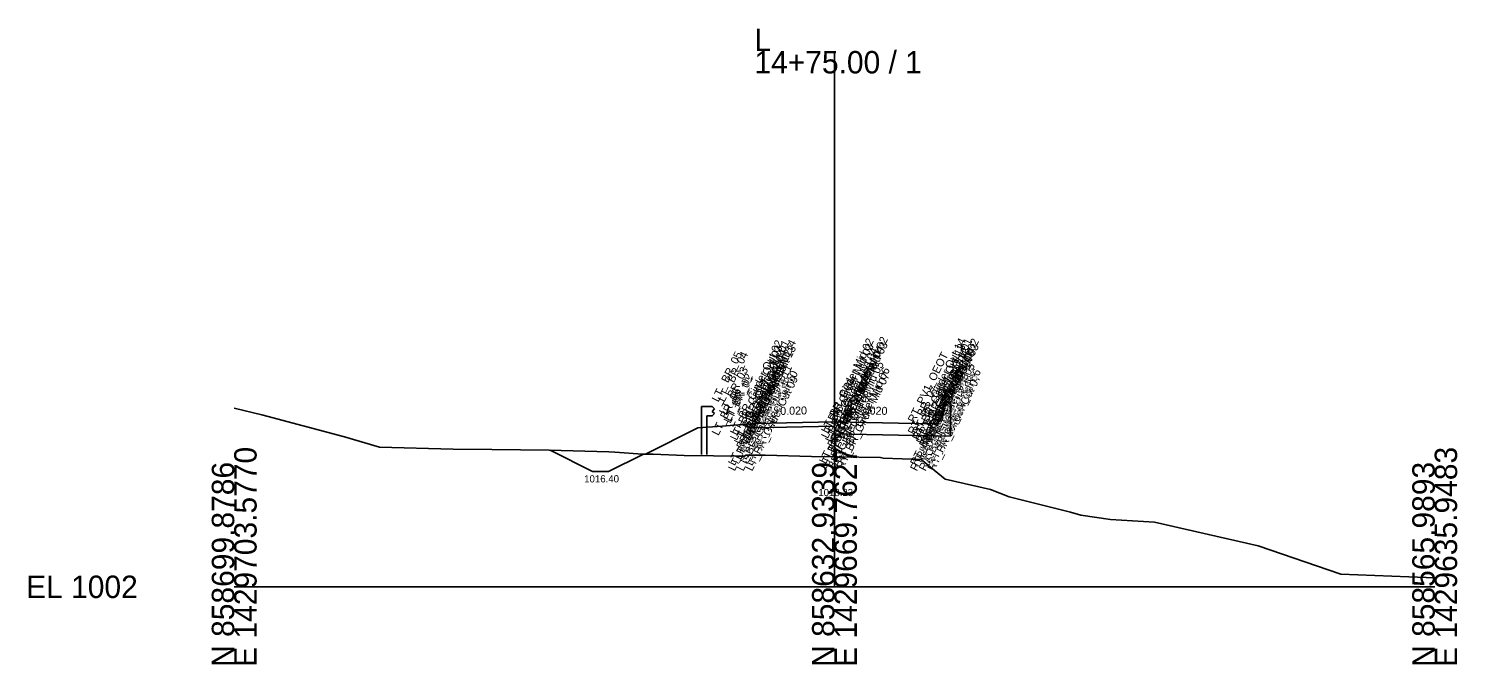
# Model space of a CAD drawing. Extents: x -26 to 153, y -10 to 13058.
# Drawn here: x -25.7 to 152.8, y 6490.3 to 6569.7 of the extents above; entities that cross this region are included whole.
import ezdxf

# ---------------------------------------------------------------- set-up
doc = ezdxf.new("R2010")
doc.units = 0
for name, color, linetype in [('Default', 7, 'Continuous'), ('Exist Cross Section Cell', 7, 'Continuous'), ('Exist XS Center Line Elevation Label', 7, 'Continuous'), ('Exist XS Ground Line', 7, 'Continuous'), ('Prop CMT Concrete Structures', 7, 'Continuous'), ('Prop CMT Guardrail Graphics', 7, 'Continuous'), ('Prop CMT Pvmt Course 1', 7, 'Continuous'), ('Prop CMT Pvmt Surface', 7, 'Continuous'), ('Prop CMT Pvmt Surface Shoulder', 7, 'Continuous'), ('Prop CMT Shld Paved Course 1', 7, 'Continuous'), ('Prop CMT Slope Grass', 7, 'Continuous'), ('Prop CMT Subgrade Earthwork', 7, 'Continuous'), ('Prop XS Dump Level', 7, 'Continuous'), ('Prop XS SE Text', 7, 'Continuous')]:
    doc.layers.add(name, color=color, linetype=linetype)

msp = doc.modelspace()

# ---------------------------------------------------------------- linework, layer by layer
at = {"layer": 'Exist Cross Section Cell'}
for p, q in [((75, 6500), (75, 6566.93)), ((0, 6500), (75, 6500)), ((75, 6500), (150, 6500))]:
    msp.add_line(p, q, dxfattribs=at)
at = {"layer": 'Exist XS Ground Line'}
msp.add_lwpolyline([(0, 6522.31), (3.44, 6521.49), (13.79, 6518.72), (18.17, 6517.45), (27.35, 6517.18), (32.2, 6517.15), (39.36, 6517.05), (46.79, 6516.88), (47.56, 6516.84), (51.03, 6516.57), (52.33, 6516.56), (56.24, 6516.42), (59.9, 6516.38), (62.96, 6516.34), (63.78, 6516.33), (63.92, 6516.46), (66.35, 6516.43), (72.14, 6516.29), (75, 6516.23), (75.38, 6516.22), (80.77, 6516.15), (81.07, 6516.09), (85.84, 6515.89), (88.82, 6513.45), (94.51, 6512.15), (96.84, 6511.22), (104.48, 6509.34), (105.79, 6508.93), (109.51, 6508.39), (114.97, 6508.07), (127.95, 6505.12), (138.29, 6501.59), (146.77, 6501.25), (150, 6501.11)], dxfattribs=at)
at = {"layer": 'Prop CMT Concrete Structures'}
for points in [[(75, 6520.61), (85, 6520.41), (88, 6520.35), (88.01, 6520.6), (88.59, 6521.43), (88.76, 6523.01), (89.5, 6523.01), (89.5, 6518.82)], [(75, 6519.11), (75, 6520.61)], [(75, 6519.11), (75, 6520.61)], [(89.5, 6518.82), (85, 6518.91), (75, 6519.11)]]:
    msp.add_lwpolyline(points, dxfattribs=at)
at = {"layer": 'Prop CMT Guardrail Graphics'}
for points in [[(58.4, 6516.51), (58.4, 6522.51)], [(58.4, 6522.51), (59.73, 6522.51), (60, 6522.22)], [(60, 6522.22), (59.73, 6521.92)], [(59.73, 6521.92), (60, 6521.63)], [(60, 6521.63), (59.73, 6521.34), (59.06, 6521.34)], [(59.06, 6521.34), (59.06, 6516.51)]]:
    msp.add_lwpolyline(points, dxfattribs=at)
at = {"layer": 'Prop CMT Pvmt Course 1'}
msp.add_line((75, 6520.61), (75, 6516.23), dxfattribs=at)
for points in [[(75, 6520.61), (65, 6520.41)], [(65, 6520.41), (65, 6519.87)], [(65, 6519.87), (75, 6520.07)]]:
    msp.add_lwpolyline(points, dxfattribs=at)
at = {"layer": 'Prop CMT Pvmt Surface'}
msp.add_lwpolyline([(75, 6520.61), (65, 6520.41)], dxfattribs=at)
at = {"layer": 'Prop CMT Pvmt Surface Shoulder'}
msp.add_lwpolyline([(65, 6520.41), (65, 6520.41)], dxfattribs=at)
at = {"layer": 'Prop CMT Shld Paved Course 1'}
for points in [[(65, 6520.41), (64.45, 6519.85)], [(65, 6520.41), (65, 6520.41)], [(65, 6519.87), (65, 6520.41)], [(64.45, 6519.85), (65, 6519.87)]]:
    msp.add_lwpolyline(points, dxfattribs=at)
at = {"layer": 'Prop CMT Slope Grass'}
for p, q in [((44.78, 6514.4), (39.48, 6517.05)), ((46.78, 6514.4), (51.06, 6516.54)), ((51.39, 6516.57), (51.06, 6516.54)), ((46.78, 6514.4), (44.78, 6514.4))]:
    msp.add_line(p, q, dxfattribs=at)
for points in [[(60.95, 6520.08), (57.95, 6519.84)], [(65, 6520.41), (60.95, 6520.08)], [(57.95, 6519.84), (51.39, 6516.57)]]:
    msp.add_lwpolyline(points, dxfattribs=at)
at = {"layer": 'Prop CMT Subgrade Earthwork'}
for points in [[(64.45, 6519.85), (63.98, 6520.33)], [(75, 6520.07), (65, 6519.87)], [(65, 6519.87), (64.45, 6519.85)]]:
    msp.add_lwpolyline(points, dxfattribs=at)

# ---------------------------------------------------------------- texts
at = {"layer": 'Default'}
for s, height, p in [('1016.40', 0.9, (43.73, 6513.04)), ('-', 0.0001, (0, 6500))]:
    msp.add_text(s, height=height, dxfattribs=at).set_placement(p)
at = {"layer": 'Exist Cross Section Cell'}
for s, p in [('L', (65, 6566.93)), ('14+75.00 / 1', (65, 6564.13)), ('EL 1002', (-26, 6498.6))]:
    msp.add_text(s, height=2.8, dxfattribs=at).set_placement(p)
for s, p in [('E 1429703.5770', (2.8, 6490)), ('E 1429669.7627', (77.8, 6490)), ('E 1429635.9483', (152.8, 6490)), ('N 858699.8786', (0, 6490)), ('N 858632.9339', (75, 6490)), ('N 858565.9893', (150, 6490))]:
    msp.add_text(s, height=2.8, rotation=90, dxfattribs=at).set_placement(p)
at = {"layer": 'Exist XS Center Line Elevation Label'}
msp.add_text('1018.23', height=0.9, dxfattribs=at).set_placement((72.98, 6511.33))
msp.add_text('1018.23', height=0.9, dxfattribs=at).set_placement((72.98, 6511.33))
msp.add_text('1018.23', height=0.9, dxfattribs=at).set_placement((72.98, 6511.33))
at = {"layer": 'Prop XS Dump Level'}
for s, p in [('LT_BR_Girder Out 02', (62.79, 6518.86)), ('LT_BR_Girder Out 14', (64.46, 6518.9)), ('LT_BR_Girder Mid 02', (74.17, 6519.09)), ('RT_BR_Girder Mid 02', (75.83, 6519.09)), ('RT_BR_Girder Out 14', (85.54, 6518.9)), ('RT_BR_Girder Out 01', (86.38, 6518.88)), ('RT_BR_Girder Out 02', (87.21, 6518.86)), ('LT_ BR_05', (60.5, 6523.01)), ('LT_ BR_04', (61.24, 6523.01)), ('LT_BR_Girder Out 03', (62.79, 6518.21)), ('LT_BR_Girder Out 04', (63.29, 6517.71)), ('LT_BR_Girder Out 01', (63.62, 6518.88)), ('LT_BR_Girder Out 12', (63.96, 6517.71)), ('LT_BR_Girder Out 13', (64.46, 6518.21)), ('LT_PV1_OEOT', (65, 6520.41)), ('LT_BR_Girder Mid 03', (74.17, 6518.44)), ('LT_BR_Girder Mid 04', (74.67, 6517.94)), ('RT_BR_Girder Mid 04', (75.33, 6517.94)), ('RT_BR_Girder Mid 03', (75.83, 6518.44)), ('RT_PV1_OEOT', (85, 6520.41)), ('RT_BR_Girder Out 13', (85.54, 6518.21)), ('RT_BR_Girder Out 12', (86.04, 6517.71)), ('RT_BR_Girder Out 04', (86.71, 6517.71)), ('RT_BR_Girder Out 03', (87.21, 6518.21)), ('RT_ BR_04', (88.76, 6523.01)), ('RT_ BR_05', (89.5, 6523.01)), ('LT_BR_03', (61.41, 6521.43)), ('LT_BR_Girder Out 05', (63.29, 6515.8)), ('LT_BR_Girder Out 11', (63.96, 6515.8)), ('LT_BR_Girder Mid 06', (73.92, 6515.27)), ('LT_BR_Girder Mid 05', (74.67, 6516.02)), ('RT_BR_Girder Mid 05', (75.33, 6516.02)), ('RT_BR_Girder Mid 06', (76.08, 6515.27)), ('RT_BR_Girder Out 10', (85.29, 6515.05)), ('RT_BR_Girder Out 11', (86.04, 6515.8)), ('RT_BR_Girder Out 05', (86.71, 6515.8)), ('RT_BR_Girder Out 06', (87.46, 6515.05)), ('RT_BR_03', (88.59, 6521.43)), ('LT_BR_02', (61.99, 6520.6)), ('LT_BR_01', (62, 6520.35)), ('LT_BR_Girder Out 06', (62.54, 6515.05)), ('LT_BR_Girder Out 07', (62.54, 6514.38)), ('LT_BR_Girder Out 08', (63.62, 6514.38)), ('LT_BR_Girder Out 10', (64.71, 6515.05)), ('LT_BR_Girder Out 09', (64.71, 6514.38)), ('LT_BR_Girder Mid 07', (73.92, 6514.61)), ('PV1_PGL', (75, 6520.61)), ('RT_BR_Girder Mid 07', (76.08, 6514.61)), ('RT_BR_Girder Out 09', (85.29, 6514.38)), ('RT_BR_Girder Out 08', (86.38, 6514.38)), ('RT_BR_Girder Out 07', (87.46, 6514.38)), ('RT_BR_01', (88, 6520.35)), ('RT_BR_02', (88.01, 6520.6)), ('LT_BR_06', (60.5, 6518.82)), ('LT_BR_07', (65, 6518.91)), ('BR_Girder Mid 08', (75, 6514.61)), ('BR_PGL', (75, 6519.11)), ('RT_BR_07', (85, 6518.91)), ('RT_BR_06', (89.5, 6518.82))]:
    msp.add_text(s, height=1, rotation=63.5833, dxfattribs=at).set_placement(p)
at = {"layer": 'Prop XS SE Text'}
for rotation, p in [(1.1458, (68.23, 6521.47)), (1.1458, (68.23, 6521.47)), (358.8542, (78.27, 6521.54))]:
    msp.add_text('0.020', height=1, rotation=rotation, dxfattribs=at).set_placement(p)

doc.saveas('drawing.dxf')
